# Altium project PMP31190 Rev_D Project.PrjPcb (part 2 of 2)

## Sheet PMP31190 Rev_D Schematic - Charger.SchDoc: Charger
size 431 x 279 mm; Date: Not shown in title block; ApprovedBy: Not shown in title block; CheckedBy: Not shown in title block; Author: Not shown in title block; CompanyName: Not shown in title block; DrawnBy: R. Scibilia; Engineer: Not shown in title block; Organization: Not shown in title block; Address1: Not shown in title block; Address2: Not shown in title block; Address3: Not shown in title block; Address4: Not shown in title block; DocumentNumber: 1; Revision: Use project parameter SCH_Rev; SheetNumber: 2; SheetTotal: 3; PageSetup: Record=PageOptions¦CenterHorizontal=True¦CenterVertical=True¦PrintScale=1.00¦XCorrection=1.00¦YCorrection=1.00¦PrintKind=0¦BorderSize=5000000¦LeftOffset=0¦BottomOffset=0¦Orientation=2¦PaperLength=1000¦PaperWidth=1000¦Scale=100¦PaperSource=15¦PrintQuality=600¦MediaType=1¦DitherType=10¦PaperKind=Letter¦PrintScaleMode=1
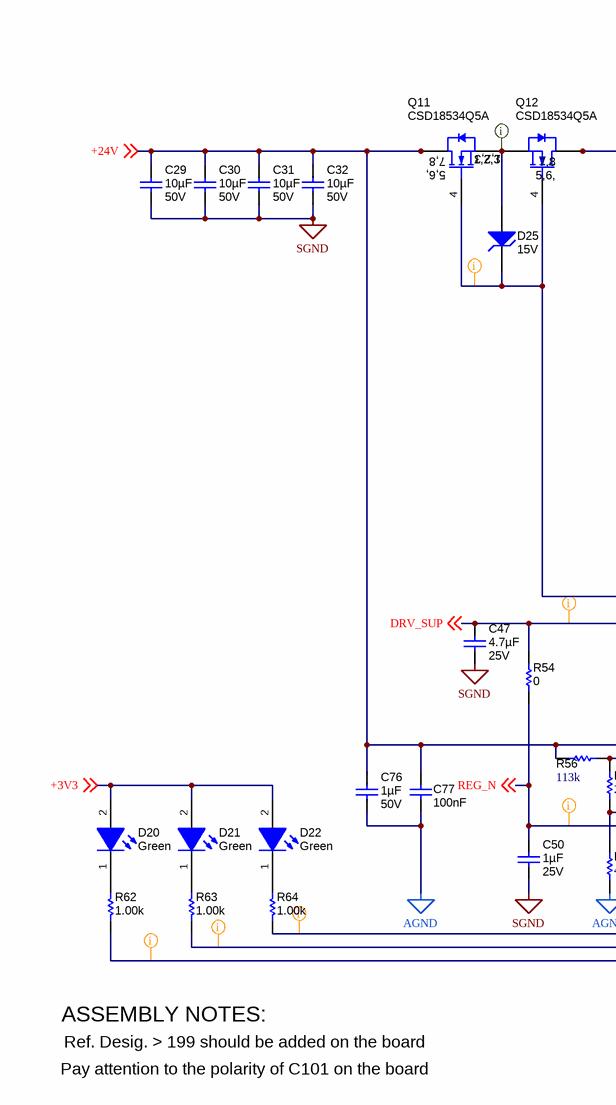
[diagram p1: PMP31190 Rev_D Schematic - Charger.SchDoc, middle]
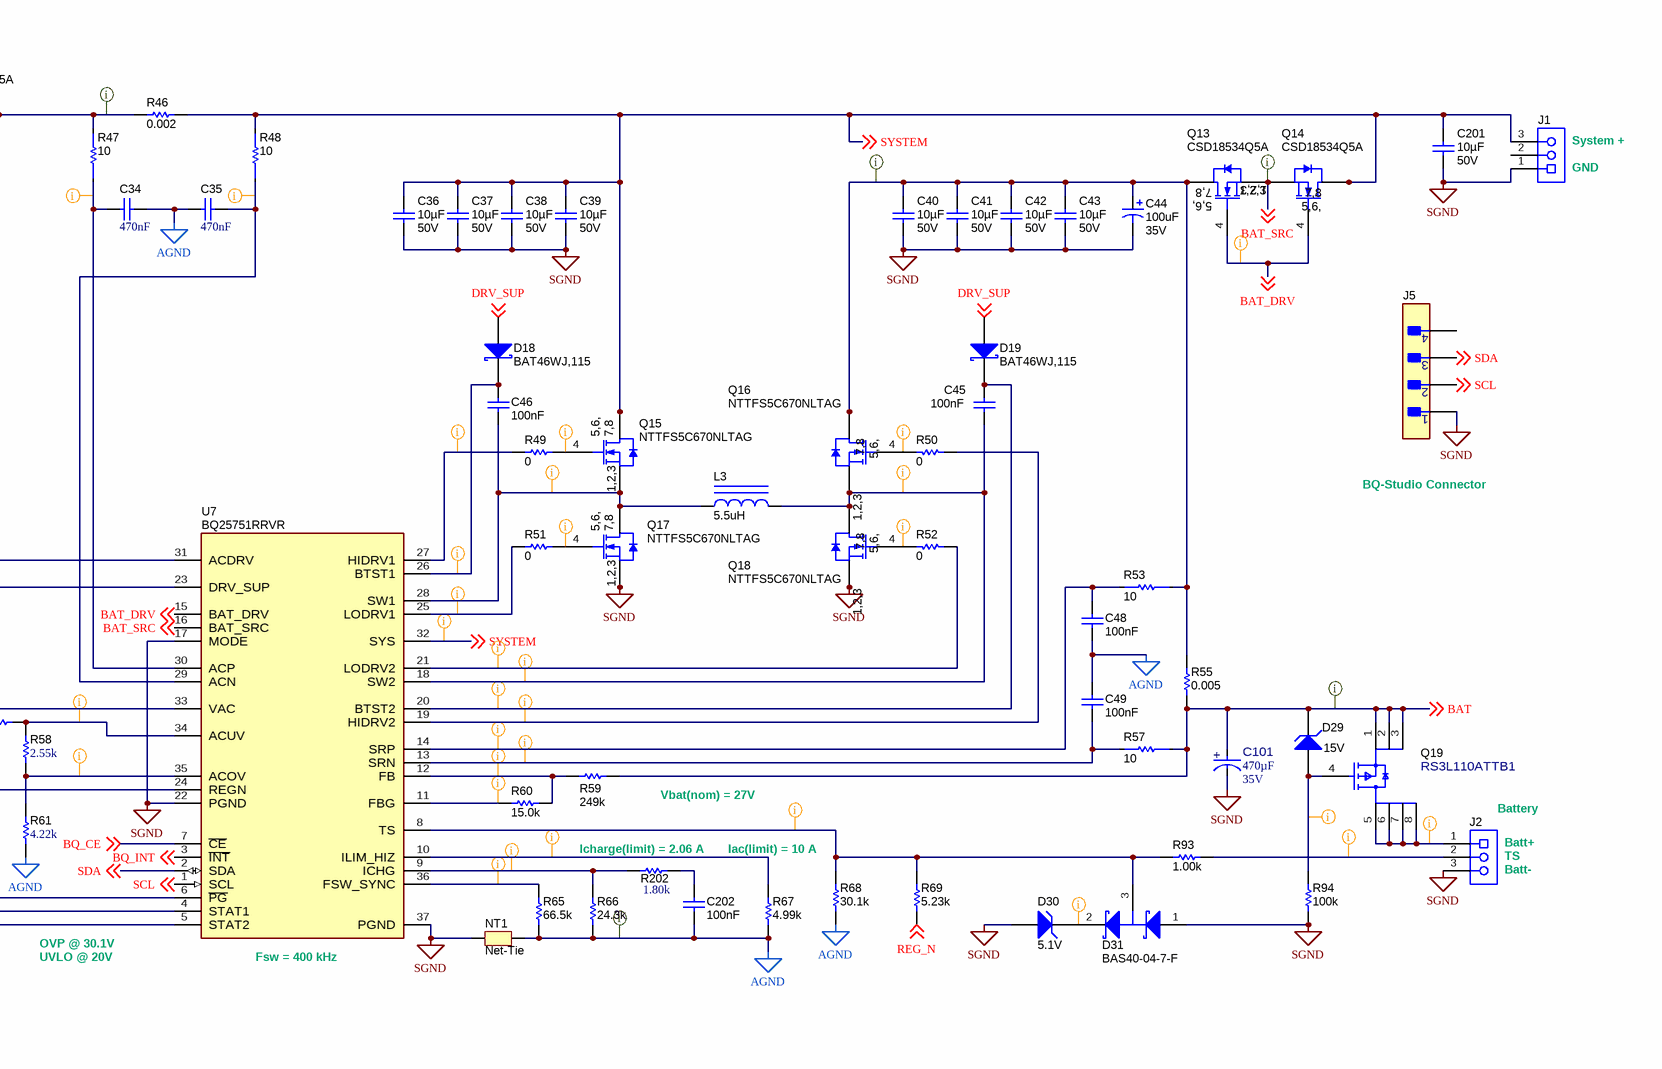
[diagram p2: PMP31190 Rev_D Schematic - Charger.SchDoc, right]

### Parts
C29  VDC_V: 50V  ValueDisplayed: 10µF  [1210_280]  (hidden comment: 885012209073)
C30  VDC_V: 50V  ValueDisplayed: 10µF  [1210_280]  (hidden comment: 885012209073)
C31  VDC_V: 50V  ValueDisplayed: 10µF  [1210_280]  (hidden comment: 885012209073)
C32  VDC_V: 50V  ValueDisplayed: 10µF  [1210_280]  (hidden comment: 885012209073)
C34  Cap_F: 470nF  [0603]  (hidden comment: CGA3E3X7R1H474K080AE)
C35  Cap_F: 470nF  [0603]  (hidden comment: CGA3E3X7R1H474K080AE)
C36  VDC_V: 50V  ValueDisplayed: 10µF  [1210_280]  (hidden comment: 885012209073)
C37  VDC_V: 50V  ValueDisplayed: 10µF  [1210_280]  (hidden comment: 885012209073)
C38  VDC_V: 50V  ValueDisplayed: 10µF  [1210_280]  (hidden comment: 885012209073)
C39  VDC_V: 50V  ValueDisplayed: 10µF  [1210_280]  (hidden comment: 885012209073)
C40  VDC_V: 50V  ValueDisplayed: 10µF  [1210_280]  (hidden comment: 885012209073)
C41  VDC_V: 50V  ValueDisplayed: 10µF  [1210_280]  (hidden comment: 885012209073)
C42  VDC_V: 50V  ValueDisplayed: 10µF  [1210_280]  (hidden comment: 885012209073)
C43  VDC_V: 50V  ValueDisplayed: 10µF  [1210_280]  (hidden comment: 885012209073)
C44  value 100uF  VDC_V: 35V  [WCAP-PTHT_1000x1250]  (hidden comment: 870135675003)
C45  Cap_F: 100nF  [0603]  (hidden comment: 885012206095)
C46  Cap_F: 100nF  [0603]  (hidden comment: 885012206095)
C47  Cap_F: 4.7µF  VDC_V: 25V  [0805_HV]  (hidden comment: 885012107018)
C48  Cap_F: 100nF  [0603]  (hidden comment: 885012206095)
C49  Cap_F: 100nF  [0603]  (hidden comment: 885012206095)
C50  Cap_F: 1µF  VDC_V: 25V  [0603]  (hidden comment: 885012206076)
C76  Cap_F: 1µF  VDC_V: 50V  [0805_HV]  (hidden comment: 885012207103)
C77  Cap_F: 100nF  [0603]  (hidden comment: 885012206095)
C101  ValueDisplayed: 470µF  VDC_V: 35V  [FP-EKZM350ELL681MJ25S_RADIAL-MFG]  (hidden comment: EKZM350ELL471MJ16S)
C201  VDC_V: 50V  ValueDisplayed: 10µF  [1210_280]  (hidden comment: 885012209073)
C202  Cap_F: 100nF  [0603]  (hidden comment: 885012206095)
D18  BAT46WJ,115  [SOD-323F]
D19  BAT46WJ,115  [SOD-323F]
D20  value Green  [WL_SMCW_GREEN_1206]  (hidden comment: 150120VS75000)
D21  value Green  [WL_SMCW_GREEN_1206]  (hidden comment: 150120VS75000)
D22  value Green  [WL_SMCW_GREEN_1206]  (hidden comment: 150120VS75000)
D25  value 15V  [SOD-323]  (hidden comment: MMSZ5245BS-7-F)
D29  value 15V  [SOD-323]  (hidden comment: MMSZ5245BS-7-F)
D30  value 5.1V  [SOD-123]  (hidden comment: MMSZ4689T3G)
D31  BAS40-04-7-F  [SOT-23L]
J1  691236510003  [Wurth_691236510003]  (value not drawn)
J2  691236510003  [Wurth_691236510003]  (value not drawn)
J5  22-05-3041  [FP-22-05-3041_HDR4-MFG]  (value not drawn)
L3  ValueDisplayed: 5.5uH  [WE-HC6]  (hidden comment: 744325550)
NT1  Net-Tie  [Net-Tie_10milWide_30milLong]  (net tie, no BOM)
Q11  CSD18534Q5A  [DQJ0008A]
Q12  CSD18534Q5A  [DQJ0008A]
Q13  CSD18534Q5A  [DQJ0008A]
Q14  CSD18534Q5A  [DQJ0008A]
Q15  NTTFS5C670NLTAG  [Power_WDFN-8]
Q16  NTTFS5C670NLTAG  [Power_WDFN-8]
Q17  NTTFS5C670NLTAG  [Power_WDFN-8]
Q18  NTTFS5C670NLTAG  [Power_WDFN-8]
Q19  RS3L110ATTB1  [FP-SQ9407EY-T1_GE3_SO-8-MFG]
R46  ValueDisplayed: 0.002  [2512]  (hidden comment: 580070763001)
R47  Res_ohm: 10  [FP-560050316012_0603-MFG]  (hidden comment: 560050316012)
R48  Res_ohm: 10  [FP-560050316012_0603-MFG]  (hidden comment: 560050316012)
R49  ValueDisplayed: 0  [0603]  (hidden comment: RMCF0603ZT0R00)
R50  ValueDisplayed: 0  [0603]  (hidden comment: RMCF0603ZT0R00)
R51  ValueDisplayed: 0  [0603]  (hidden comment: RMCF0603ZT0R00)
R52  ValueDisplayed: 0  [0603]  (hidden comment: RMCF0603ZT0R00)
R53  Res_ohm: 10  [FP-560050316012_0603-MFG]  (hidden comment: 560050316012)
R54  ValueDisplayed: 0  [0603]  (hidden comment: RMCF0603ZT0R00)
R55  ValueDisplayed: 0.005  [2512]  (hidden comment: 580070763005)
R56  ValueDisplayed: 113k  [0603]  (hidden comment: RC0603FR-07113KL)
R57  Res_ohm: 10  [FP-560050316012_0603-MFG]  (hidden comment: 560050316012)
R58  ValueDisplayed: 2.55k  [0603]  (hidden comment: RC0603FR-072K55L)
R59  ValueDisplayed: 249k  [0603]  (hidden comment: RC0603FR-07249KL)
R60  ValueDisplayed: 15.0k  [0603]  (hidden comment: RC0603FR-0715KL)
R61  ValueDisplayed: 4.22k  [0603]  (hidden comment: RT0603DRE074K22L)
R62  ValueDisplayed: 1.00k  [0603]  (hidden comment: RC0603FR-071KL)
R63  ValueDisplayed: 1.00k  [0603]  (hidden comment: RC0603FR-071KL)
R64  ValueDisplayed: 1.00k  [0603]  (hidden comment: RC0603FR-071KL)
R65  ValueDisplayed: 66.5k  [0603]  (hidden comment: RC0603FR-0766K5L)
R66  ValueDisplayed: 24.3k  [0603]  (hidden comment: CRCW060324K3FKEA)
R67  ValueDisplayed: 4.99k  [0603]  (hidden comment: RC0603FR-074K99L)
R68  ValueDisplayed: 30.1k  [0603]  (hidden comment: RT0603BRD0730K1L)
R69  ValueDisplayed: 5.23k  [0603]  (hidden comment: RT0603BRD075K23L)
R93  ValueDisplayed: 1.00k  [2010]  (hidden comment: CRCW20101K00FKEF)
R94  ValueDisplayed: 100k  [0603]  (hidden comment: CRCW0603100KDHEAP)
R202  ValueDisplayed: 1.80k  [0603]  (hidden comment: RC0603FR-071K8L)
U7  BQ25751RRVR  [RRV0036A-MFG]

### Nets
AGND: C34.1 C35.2 C48.1 C49.2 C76.2 C77.1 C202.1 NT1.2 R61.1 R65.1 R66.1 R67.1 R68.1
SGND: C29.2 C30.2 C31.2 C32.2 C36.2 C37.2 C38.2 C39.2 C40.2 C41.2 C42.2 C43.2 C44.2(-) C47.2 C50.1 C101.1(CATHODE) C201.2 D30.2(A) D31.1(A) J1.1 J2.3 J5.1 NT1.1 Q17.1(S) Q17.2(S) Q17.3(S) Q18.1(S) Q18.2(S) Q18.3(S) R94.1 U7.17(MODE) U7.22(PGND) U7.37(PGND)
+3V3: D20.2(A) D21.2(A) D22.2(A) ; off-sheet +3V3
+24V: C29.1 C30.1 C31.1 C32.1 C76.1 C77.2 Q11.5(D) Q11.6(D) Q11.7(D) Q11.8(D) Q11.9(D) R56.2 U7.33(VAC) ; off-sheet +24V
BAT: C101.2(ANODE) D29.1(K) Q19.1(S) Q19.2(S) Q19.3(S) R55.1 R57.1 R59.1 ; off-sheet BAT
BAT_DRV: Q13.4(G) Q14.4(G) U7.15(BAT_DRV) ; off-sheet BAT_DRV
BAT_SRC: Q13.1(S) Q13.2(S) Q13.3(S) Q14.1(S) Q14.2(S) Q14.3(S) U7.16(BAT_SRC) ; off-sheet BAT_SRC
BQ_CE: U7.7(~{CE}) ; off-sheet BQ_CE
BQ_INT: U7.3(~{INT}) ; off-sheet BQ_INT
DRV_SUP: C47.1 D18.2(A) D19.2(A) R54.2 U7.23(DRV_SUP) ; off-sheet DRV_SUP
REG_N: C50.2 R54.1 R69.2 U7.24(REGN) ; off-sheet REG_N
SCL: J5.2 U7.1(SCL) ; off-sheet SCL
SDA: J5.3 U7.2(SDA) ; off-sheet SDA
SYSTEM: C36.1 C37.1 C38.1 C39.1 C201.1 J1.3 Q14.5(D) Q14.6(D) Q14.7(D) Q14.8(D) Q14.9(D) Q15.5(D) Q15.6(D) Q15.7(D) Q15.8(D) Q15.9(D) R46.2 R48.2 U7.32(SYS) ; off-sheet SYSTEM
NetC34_2: C34.2 R47.1 U7.30(ACP)
NetC35_1: C35.1 R48.1 U7.29(ACN)
NetC40_1: C40.1 C41.1 C42.1 C43.1 C44.1(+) Q13.5(D) Q13.6(D) Q13.7(D) Q13.8(D) Q13.9(D) Q16.5(D) Q16.6(D) Q16.7(D) Q16.8(D) Q16.9(D) R53.1 R55.2
NetC45_1: C45.1 L3.2 Q16.1(S) Q16.2(S) Q16.3(S) Q18.5(D) Q18.6(D) Q18.7(D) Q18.8(D) Q18.9(D) U7.18(SW2)
NetC45_2: C45.2 D19.1(K) U7.20(BTST2)
NetC46_1: C46.1 L3.1 Q15.1(S) Q15.2(S) Q15.3(S) Q17.5(D) Q17.6(D) Q17.7(D) Q17.8(D) Q17.9(D) U7.28(SW1)
NetC46_2: C46.2 D18.1(K) U7.26(BTST1)
NetC48_2: C48.2 R53.2 U7.14(SRP)
NetC49_1: C49.1 R57.2 U7.13(SRN)
NetC202_2: C202.2 R202.1
NetD20_1: D20.1(K) R62.1
NetD21_1: D21.1(K) R63.1
NetD22_1: D22.1(K) R64.1
NetD25_1: D25.1(K) Q11.4(G) Q12.4(G) U7.31(ACDRV)
NetD25_2: D25.2(A) Q11.1(S) Q11.2(S) Q11.3(S) Q12.1(S) Q12.2(S) Q12.3(S)
NetD29_2: D29.2(A) Q19.4(G) R94.2
NetD30_1: D30.1(K) D31.2(K)
NetD31_3: D31.3(C) R68.2 R69.1 R93.1 U7.8(TS)
NetJ2_1: J2.1 Q19.5(D) Q19.6(D) Q19.7(D) Q19.8(D)
NetJ2_2: J2.2 R93.2
NetQ12_5: Q12.5(D) Q12.6(D) Q12.7(D) Q12.8(D) Q12.9(D) R46.1 R47.2
NetQ15_4: Q15.4(G) R49.2
NetQ16_4: Q16.4(G) R50.1
NetQ17_4: Q17.4(G) R51.1
NetQ18_4: Q18.4(G) R52.1
NetR49_1: R49.1 U7.27(HIDRV1)
NetR50_2: R50.2 U7.19(HIDRV2)
NetR51_2: R51.2 U7.25(LODRV1)
NetR52_2: R52.2 U7.21(LODRV2)
NetR56_1: R56.1 R58.2 U7.34(ACUV)
NetR58_1: R58.1 R61.2 U7.35(ACOV)
NetR59_2: R59.2 R60.1 U7.12(FB)
NetR60_2: R60.2 U7.11(FBG)
NetR62_2: R62.2 U7.5(STAT2)
NetR63_2: R63.2 U7.4(STAT1)
NetR64_2: R64.2 U7.6(~{PG})
NetR65_2: R65.2 U7.36(FSW_SYNC)
NetR66_2: R66.2 R202.2 U7.9(ICHG)
NetR67_2: R67.2 U7.10(ILIM_HIZ)

Not connected (* = marked no-connect by the designer): J1 2; J5 4

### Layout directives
rule Clearance Constraint [Clearance = 10mil]: AGND, BAT, BAT_SRC, NetC40_1, NetD25_2, NetQ12_5
rule Clearance Constraint [Clearance = 9mil]: BAT_DRV, DRV_SUP, NetC34_2, NetC35_1, NetC45_1, NetC45_2, NetC46_1, NetC46_2, NetC48_2, NetC49_1, NetD25_1, NetD29_2, NetD30_1, NetD31_3, NetJ2_1, NetJ2_2, NetQ15_4, NetQ16_4, NetQ17_4, NetQ18_4, NetR49_1, NetR50_2, NetR51_2, NetR52_2, NetR56_1, NetR58_1, NetR59_2, NetR60_2, NetR62_2, NetR63_2, NetR64_2, NetR65_2, NetR66_2, NetR67_2, REG_N, SYSTEM

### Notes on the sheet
- (near J1) System +
- (near J1) GND
- BQ-Studio Connector
- (near R202) Icharge(limit) = 2.06 A
- Vbat(nom) = 27V
- Iac(limit) = 10 A
- (near J2) Battery
- (near J2) Batt+
- (near J2) Batt-
- (near J2) TS
- ASSEMBLY NOTES:
- UVLO @ 20V
- OVP @ 30.1V
- (near U7) Fsw = 400 kHz
- Pay attention to the polarity of C101 on the board
- Ref. Desig. > 199 should be added on the board

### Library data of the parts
C29-C32 C36-C43 C201 = CMP-0081135-1: CAP, CERM, 10 µF, 50 V,+/- 10%, X7R, 1210; Manufacturer: Wuerth; TaMin_C: -55°C; ESR_ohm: 1m; Polarized: N; SizeAreaWB_mm2: 14.7; Value1: 0.001 ohm; U/M: EA; Value: 10uF; TaMax_C: 125°C; SizeZ_mm: 2.8; SizeX_mm: 3.2; SizeY_mm: 2.5; Cap_Case: 1210; SizeArea_mm2: 8; AEC Category: Q200
C34 C35 = CMP-0007097-4: CAP, CERM, 0.47 uF, 50 V, +/- 10%, X7R, AEC-Q200 Grade 1, 0603; Manufacturer: TDK; TaMin_C: -55°C; Polarized: N; SizeAreaWB_mm2: 4.68; Value1: Unknown; U/M: EA; Value: 0.47uF; TaMax_C: 125°C; SizeZ_mm: 1; SizeX_mm: 1.6; SizeY_mm: 0.8; Value2: 50V; SizeArea_mm2: 1.28; AEC Qualified: Y; AEC Category: Q200
C44 = CMP-0079638-1: CAP, Aluminum Polymer, 100 µF, 35 V,+/- 20%, 0.022 ohm, TH; Manufacturer: Wurth Elektronik; SizeAreaWB_mm2: 144; SizeArea_mm2: 100; AEC Qualified: N; AEC Category: Q200; TaMax_C: 125°C; SizeZ_mm: 14; Polarized: Y; TaMin_C: -55°C; SizeY_mm: 10; CompType: Capacitor; ESR_ohm: 22m; Cap_Case: 10x14mm; ValueDisplayed: 100µF
C45 C46 C48 C49 C77 C202 = CMP-0006837-3: CAP, CERM, 0.1 uF, 50 V, +/- 10%, X7R, 0603; Manufacturer: Wurth Elektronik; TaMin_C: -55°C; Polarized: N; SizeAreaWB_mm2: 4.68; Value1: Unknown; U/M: EA; Value: 0.1uF; TaMax_C: 125°C; SizeZ_mm: 1; SizeX_mm: 1.6; SizeY_mm: 0.8; Value2: 50V; SizeArea_mm2: 1.28; AEC Category: Q200
C47 = CMP-0007696-2: CAP, CERM, 4.7 uF, 25 V, +/- 10%, X5R, 0805; Manufacturer: Wurth Elektronik; TaMin_C: -55°C; Polarized: N; SizeAreaWB_mm2: 6.75; Value1: Unknown; U/M: EA; Value: 4.7uF; TaMax_C: 125°C; SizeZ_mm: 1.45; SizeX_mm: 2; SizeY_mm: 1.25; Cap_Case: 0805; SizeArea_mm2: 2.5; AEC Category: Q200
C50 = CMP-0006833-4: CAP, CERM, 1 uF, 25 V, +/- 10%, X7R, 0603; Manufacturer: Wurth Elektronik; TaMin_C: -55°C; Polarized: N; SizeAreaWB_mm2: 4.68; Value1: Unknown; U/M: EA; Value: 1uF; TaMax_C: 125°C; SizeZ_mm: 1; SizeX_mm: 1.6; SizeY_mm: 0.8; SizeArea_mm2: 1.28; AEC Category: Q200
C76 = CMP-0007696-2: CAP, CERM, 1 uF, 50 V, +/- 10%, X7R, 0805; Manufacturer: Wurth Elektronik; TaMin_C: -55°C; Polarized: N; SizeAreaWB_mm2: 6.75; Value1: Unknown; U/M: EA; Value: 1uF; TaMax_C: 125°C; SizeZ_mm: 1.45; SizeX_mm: 2; SizeY_mm: 1.25; Cap_Case: 0805; SizeArea_mm2: 2.5; AEC Category: Q200
C101 = CMP-0001423-1: Cap Aluminum 470uF 35V 20% (10 X 16mm) Radial 5mm; Manufacturer: United Chemi-Con; AEC Qualified: No; IRMS_A: 1.96A; Dissipation Factor: 12%; Leakage Current: 238uA; Life: 10000Hours; Value: 470µF
D18 D19 = CMP-0076946-2: Diode, Schottky, 100 V, 0.25 A, SOD-323F; Manufacturer: Nexperia; SizeAreaWB_mm2: 7.875; Value2: 0.85V; SizeX_mm: 2.5; Green_REACh: Incomplete; SizeArea_mm2: 3.125; Vf_V: 850mV; Green_Lifecycle: Not Set; Vr_V: 100V; TJmax_C: 150°C; Value1: 0.25A; Io_A: 250mA; SizeZ_mm: 0.8; Value: 100V; AEC Category: Q101; SizeY_mm: 1.25
D20-D22 = CMP-0002936-3: LED, Green, SMD; Manufacturer: Wurth Elektronik; Vr_V: 5V; Power_TotalModule: 72mW; Value2: 2V; Value1: 0.072W; Angle: 140; Type: AlInGaP; Io_A: 20mA; Ir_A: 10µA; Tjmax_C: 85°C
D25 D29 = CMP-0005833-4: Diode, Zener, 15 V, 200 mW, SOD-323; Manufacturer: Diodes Inc.; SizeY_mm: 1.35; RJA_CperW: 350; SizeX_mm: 2.7; AEC Category: Q101; SizeAreaWB_mm2: 8.695; SizeZ_mm: 1; Power_W: 200mW; SizeArea_mm2: 3.645; Value1: 0.2W
D30 = CMP-0005786-2: Diode, Zener, 5.1 V, 500 mW, SOD-123; Manufacturer: ON Semiconductor; SizeZ_mm: 1.35; AEC Category: Q101; Power_W: 500mW; SizeArea_mm2: 6.545; SizeX_mm: 3.85; RJA_CperW: 340; SizeY_mm: 1.7; Value1: 0.5W; SizeAreaWB_mm2: 13.095
D31 = CMP-0076970-1: Diode, Schottky, 40 V, 0.2 A, SOT-23; Manufacturer: Diodes Inc.; SizeAreaWB_mm2: 14.0; Vr_V: 40V; SizeArea_mm2: 7.5; TJmax_C: 125°C; AEC Category: Q101; Value: 40V; SizeZ_mm: 1.1; Green_REACh: Incomplete; Io_A: 200mA; Vf_V: 1V; SizeY_mm: 3.0; Green_Lifecycle: Not Set; U/M: EA; Value1: 0.2A; SizeX_mm: 2.5
J1 J2 = CMP-0079043-1: Terminal Block, 5.08mm, 3x1, R/A, TH; Manufacturer: Wurth Elektronik; Pitch_mm: 5.08; Cert_VDE: Y; Gender: Female; Voltage_V: 300V; Current_A: 20A; Row_Count: 1
J5 = CMP-0089047-1: Manufacturer: Molex; Current_A: 4A; Row_Count: 1; Voltage_V: 500V; ContactFinish: Tin,Nickel
L3 = CMP-0063967-1: Inductor, Shielded Drum Core, Superflux, 5.5 uH, 10 A, 0.0112 ohm, SMD; Manufacturer: Wurth Elektronik; Isat: 12A @ 30% inductance drop; Irms: 10A @ 50C rise; Green_Lifecycle: Active; SizeAreaWB_mm2: 158.6; DCR_ohm: 11.2m; Green_REACh: Passed; Value: 5.5uH; Imax_A: 10A; SizeZ_mm: 5; SizeX_mm: 11; SizeY_mm: 10.2; SizeArea_mm2: 112.2; Ind_H: 5.5µH; AEC Category: Q200
NT1 = CMP-0078142-5: Single point connection between nets.
Q11-Q14 = CMP-0000817-1: MOSFET, N-CH, 60 V, 50 A, DQJ0008A (VSONP-8); Alternate Manufacturer: None; Manufacturer: Texas Instruments; SizeZ_mm: 1.1; ChType: N; Value2: 22 nC; Value1: 0.009; VdsMax_V: 60V; SizeX_mm: 6; SizeY_mm: 4.9; Vgs_V: 2.3V; Value: 60V; Rdson45_ohm: 9.8m; SizeArea_mm2: 29.4; AEC Category: Q101; IdsMax_A: 50A; SizeAreaWB_mm2: 55.2; U/M: EA; QgTyp_nC: 22
Q15-Q18 = CMP-0000855-1: MOSFET, N-CH, 60 V, 70 A, 8-PowerWDFN; Alternate Manufacturer: None; Manufacturer: ON Semiconductor; SizeZ_mm: 0.8; ChType: N; Value2: 9 nC; Value1: 0.013; VdsMax_V: 60V; SizeX_mm: 3.3; Vgs_V: 20V; Rdson45_ohm: 13.3m; SizeArea_mm2: 10.89; AEC Category: Q101; IdsMax_A: 70A; SizeAreaWB_mm2: 18.49; U/M: EA; QgTyp_nC: 9.5
Q19 = CMP-0093692-1: P-Channel 60 V 4.6A (Tc) 3.75W (Tc) Surface Mount 8-SOIC; Manufacturer: Rohm Semiconductor; Number Of P Channels: 1; Rdson45_ohm: 12.8m; IdsMax_A: -11A; AEC Grade: Grade 0; ChMode: False; Rthja Max: 100°C/W; Pulse Drain Current: -44A; Standoff Height: 0.1mm; AEC Qualified: Yes; QgTyp_nC: 115nC @ -10V; SizeZ_mm: 1.75mm; Turn On Delay Time: 11ns; Transconductance: 10S; TJmax_C: +175°C; Threshold Vgs Max: -2.5V; Typ Forward Diode Voltage: -0.84V; Vgs_V: 20V; Threshold Vgs Min: -1.5V; Input Capacitace At Vds: 6300pF @ -30V; VdsMax_V: -1.1V; Drain To Source Breakdown Voltage: -60V; Turn Off Delay Time: 36ns; Power_W: 1.4W
R46 = CMP-0015819-2: RES, 0.002, 1%, 2 W, 2512; Manufacturer: Wuerth; Power_W: 2W; TempCo: ppm/C; Value_Code: 2L000; U/M: EA; Value: 0.002; Res_ohm: 2m; SizeX_mm: 6.3; SizeY_mm: 3.2; SizeZ_mm: 0.71; SizeArea_mm2: 20.16; AEC Category: Q200
R47 R48 R53 R57 = CMP-0087986-1: WRIS-KSKE Thick Film Resistors; Manufacturer: Wurth Electronics; Tolerance_%: 1%; AEC Qualified: No; TempCo: 100ppm/°C; Symbol Name: SYM-560050316012; Power_W: 250mW; SizeZ_mm: 0.55mm; VDC_V: 1.5811V
R49-R52 R54 = CMP-0023343-3: RES, 0, 1%, 0.1 W, AEC-Q200 Grade 0, 0603; Manufacturer: Stackpole Electronics Inc; Power_W: 100mW; TempCo: ppm/C; U/M: EA; Value: 0; SizeX_mm: 1.6; SizeY_mm: 0.8; SizeZ_mm: 1; Value2: 0.1W; SizeArea_mm2: 1.28; AEC Qualified: Y; AEC Category: Q200
R55 = CMP-0015814-2: RES, 0.005, 1%, 2 W, 2512; Manufacturer: Wuerth; Power_W: 2W; TempCo: 100 ppm/C; Value_Code: 5L000; U/M: EA; Value: 0.005; EIA_Code: E96; Res_ohm: 5m; SizeX_mm: 6.3; SizeY_mm: 3.2; SizeZ_mm: 0.71; SizeArea_mm2: 20.16; AEC Category: Q200
R56 = CMP-0022754-4: RES, 113 k, 1%, 0.1 W, 0603; Manufacturer: Yageo; Power_W: 100mW; TempCo: 100 ppm/C; Value: 113k; EIA_Code: E96; SizeX_mm: 1.6; SizeY_mm: 0.8; SizeZ_mm: 1; Value2: 0.1W; SizeArea_mm2: 1.28; AEC Qualified: N; VDC_V: 75V; AEC Category: Q200; SizeAreaWB_mm2: 4.68
R58 = CMP-0022992-5: RES, 2.55 k, 1%, 0.1 W, 0603; Manufacturer: Yageo; Power_W: 100mW; TempCo: 100 ppm/C; Value_Code: 2k55; Value: 2.55k; EIA_Code: E96; SizeX_mm: 1.6; SizeY_mm: 0.8; SizeZ_mm: 1; Value2: 0.1W; SizeArea_mm2: 1.28; AEC Qualified: N; VDC_V: 75V; AEC Category: Q200; SizeAreaWB_mm2: 4.68
R59 = CMP-0022941-4: RES, 249 k, 1%, 0.1 W, 0603; Manufacturer: Yageo; Power_W: 100mW; TempCo: 100 ppm/C; Value: 249k; EIA_Code: E96; SizeX_mm: 1.6; SizeY_mm: 0.8; SizeZ_mm: 1; Value2: 0.1W; SizeArea_mm2: 1.28; AEC Qualified: N; VDC_V: 75V; AEC Category: Q200; SizeAreaWB_mm2: 4.68
R60 = CMP-0022816-5: RES, 15.0 k, 1%, 0.1 W, 0603; Manufacturer: Yageo; Power_W: 100mW; TempCo: 100 ppm/C; Value_Code: 15k0; Value: 15.0k; EIA_Code: E96; Res_ohm: 15k; SizeX_mm: 1.6; SizeY_mm: 0.8; SizeZ_mm: 1; Value2: 0.1W; SizeArea_mm2: 1.28; AEC Qualified: N; VDC_V: 75V; AEC Category: Q200; SizeAreaWB_mm2: 4.68
R61 = CMP-0025339-3: RES, 4.22 k, 0.5%, 0.1 W, 0603; Manufacturer: Yageo America; Power_W: 100mW; TempCo: 50 ppm/C; Value_Code: 4k22; U/M: EA; Value: 4.22k; EIA_Code: E192; SizeX_mm: 1.6; SizeY_mm: 0.8; SizeZ_mm: 1; Value2: 0.1W; SizeArea_mm2: 1.28; VDC_V: 75V; AEC Category: Q200
R62-R64 = CMP-0022895-5: RES, 1.00 k, 1%, 0.1 W, 0603; Manufacturer: Yageo; Power_W: 100mW; TempCo: 100 ppm/C; Value_Code: 1k00; Value: 1.00k; EIA_Code: E96; Res_ohm: 1k; SizeX_mm: 1.6; SizeY_mm: 0.8; SizeZ_mm: 1; Value2: 0.1W; SizeArea_mm2: 1.28; AEC Qualified: N; VDC_V: 75V; AEC Category: Q200; SizeAreaWB_mm2: 4.68
R65 = CMP-0023232-5: RES, 66.5 k, 1%, 0.1 W, 0603; Manufacturer: Yageo; Power_W: 100mW; TempCo: 100 ppm/C; Value_Code: 66k5; Value: 66.5k; EIA_Code: E96; SizeZ_mm: 1; Value2: 0.1W; SizeArea_mm2: 1.28; AEC Qualified: N; VDC_V: 75V; AEC Category: Q200; SizeAreaWB_mm2: 4.68; SizeX_mm: 1.6; SizeY_mm: 0.8
R66 = CMP-0022236-4: RES, 24.3 k, 1%, 0.1 W, AEC-Q200 Grade 0, 0603; Manufacturer: Vishay-Dale; Power_W: 100mW; TempCo: 100 ppm/C; Value_Code: 24k3; Value: 24.3k; EIA_Code: E96; SizeX_mm: 1.6; SizeY_mm: 0.8; SizeZ_mm: 1; Value2: 0.1W; SizeArea_mm2: 1.28; AEC Qualified: Y; VDC_V: 75V; AEC Category: Q200; AEC Grade: 0
R67 = CMP-0023155-5: RES, 4.99 k, 1%, 0.1 W, 0603; Manufacturer: Yageo; Power_W: 100mW; TempCo: 100 ppm/C; Value_Code: 4k99; Value: 4.99k; EIA_Code: E96; SizeX_mm: 1.6; SizeY_mm: 0.8; SizeZ_mm: 1; Value2: 0.1W; SizeArea_mm2: 1.28; AEC Qualified: N; VDC_V: 75V; AEC Category: Q200; SizeAreaWB_mm2: 4.68
R68 = CMP-0024096-3: RES, 30.1 k, 0.1%, 0.1 W, 0603; Manufacturer: Yageo America; Power_W: 100mW; TempCo: 25 ppm/C; Value_Code: 30k1; U/M: EA; Value: 30.1k; EIA_Code: E192; SizeX_mm: 1.6; SizeY_mm: 0.8; SizeZ_mm: 1; Value2: 0.1W; SizeArea_mm2: 1.28; VDC_V: 75V; AEC Category: Q200
R69 = CMP-0024368-2: RES, 5.23 k, 0.1%, 0.1 W, 0603; Manufacturer: Yageo America; Power_W: 100mW; TempCo: 25 ppm/C; Value_Code: 5k23; U/M: EA; Value: 5.23k; EIA_Code: E192; SizeX_mm: 1.6; SizeY_mm: 0.8; SizeZ_mm: 1; Value2: 0.1W; SizeArea_mm2: 1.28; VDC_V: 75V; AEC Category: Q200
R93 = CMP-0016277-2: RES, 1.00 k, 1%, 0.75 W, AEC-Q200 Grade 0, 2010; Manufacturer: Vishay-Dale; Power_W: 750mW; TempCo: 100 ppm/C; Value_Code: 1k00; U/M: EA; Value: 1.00k; EIA_Code: E96; Res_ohm: 1k; SizeX_mm: 5; SizeY_mm: 2.5; SizeZ_mm: 1.66; Value2: 0.75W; SizeArea_mm2: 12.5; AEC Qualified: Y; VDC_V: 400V; AEC Grade: 0; AEC Category: Q200
R94 = CMP-0086261-1: RES, 100 k, 0.5%, 0.1 W, AEC-Q200 Grade 0, 0603; Manufacturer: Vishay-Dale; EIA_Code: E192; SizeZ_mm: 1; Power_W: 100mW; Value2: 0.1W; Value: 100k; SizeAreaWB_mm2: 4.68; AEC Qualified: Y; TempCo: 50 ppm/C; SizeArea_mm2: 1.28; AEC Category: Q200; SizeX_mm: 1.6; SizeY_mm: 0.8; AEC Grade: 0
R202 = CMP-0022892-5: RES, 1.80 k, 1%, 0.1 W, 0603; Manufacturer: Yageo; Power_W: 100mW; TempCo: 100 ppm/C; Value_Code: 1k80; Value: 1.80k; Res_ohm: 1.8k; SizeX_mm: 1.6; SizeY_mm: 0.8; SizeZ_mm: 1; Value2: 0.1W; SizeArea_mm2: 1.28; AEC Qualified: N; VDC_V: 75V; AEC Category: Q200; SizeAreaWB_mm2: 4.68
U7 = CMP-0093459-1: 70V, buck-boost, lead acid battery charge controller; Manufacturer: Texas Instruments; SizeZ_mm: 1mm; Standoff Height: 0mm; AEC Qualified: No

## Sheet PMP31190 Rev_D Schematic - LaunchPad Interface.SchDoc: LaunchPad / AC sense / aux supply
size 431 x 279 mm; Date: Not shown in title block; ApprovedBy: Not shown in title block; CheckedBy: Not shown in title block; Author: Not shown in title block; CompanyName: Not shown in title block; DrawnBy: R. Scibilia; Engineer: Not shown in title block; Organization: Not shown in title block; Address1: Not shown in title block; Address2: Not shown in title block; Address3: Not shown in title block; Address4: Not shown in title block; DocumentNumber: 1; Revision: Use project parameter SCH_Rev; SheetNumber: 3; SheetTotal: 3; PageSetup: Record=PageOptions¦CenterHorizontal=True¦CenterVertical=True¦PrintScale=1.00¦XCorrection=1.00¦YCorrection=1.00¦PrintKind=0¦BorderSize=5000000¦LeftOffset=0¦BottomOffset=0¦Orientation=2¦PaperLength=1000¦PaperWidth=1000¦Scale=100¦PaperSource=15¦PrintQuality=600¦MediaType=1¦DitherType=10¦PaperKind=Letter¦PrintScaleMode=1
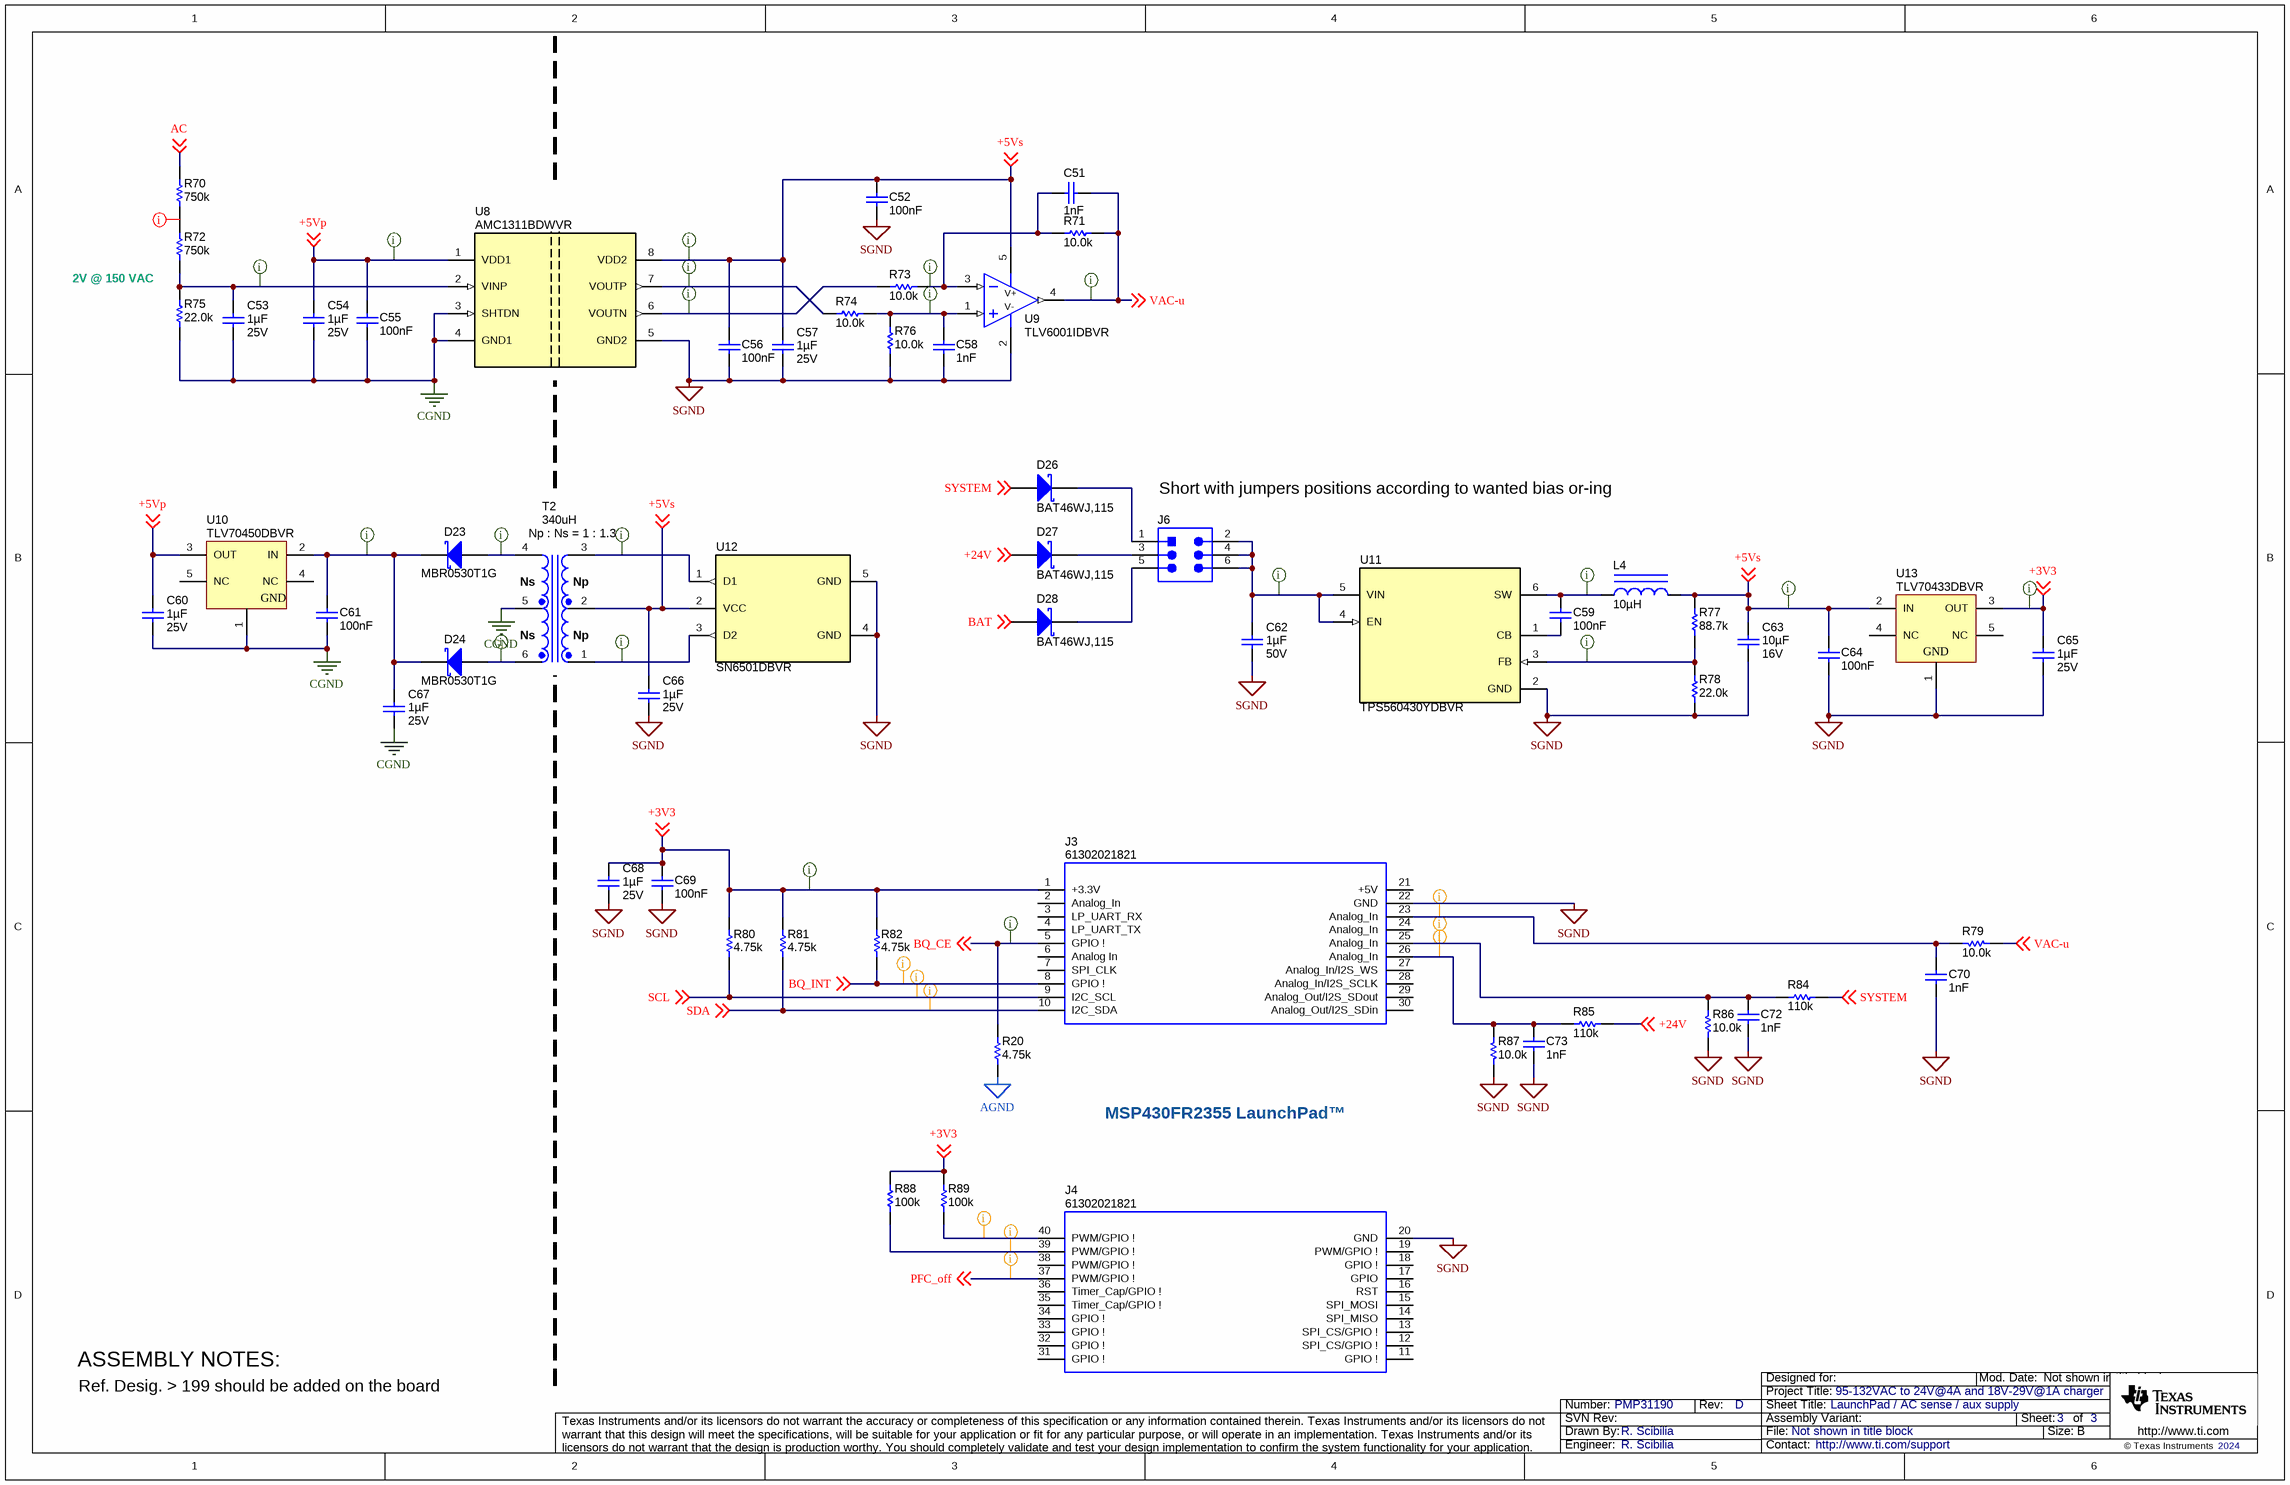
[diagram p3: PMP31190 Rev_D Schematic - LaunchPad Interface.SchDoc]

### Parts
C51  Cap_F: 1nF  [0603]  (hidden comment: 885012206083)
C52  Cap_F: 100nF  [0603]  (hidden comment: 885012206095)
C53  Cap_F: 1µF  VDC_V: 25V  [0603]  (hidden comment: 885012206076)
C54  Cap_F: 1µF  VDC_V: 25V  [0603]  (hidden comment: 885012206076)
C55  Cap_F: 100nF  [0603]  (hidden comment: 885012206095)
C56  Cap_F: 100nF  [0603]  (hidden comment: 885012206095)
C57  Cap_F: 1µF  VDC_V: 25V  [0603]  (hidden comment: 885012206076)
C58  Cap_F: 1nF  [0603]  (hidden comment: 885012206083)
C59  Cap_F: 100nF  [0603]  (hidden comment: 885012206095)
C60  Cap_F: 1µF  VDC_V: 25V  [0603]  (hidden comment: 885012206076)
C61  Cap_F: 100nF  [0603]  (hidden comment: 885012206095)
C62  Cap_F: 1µF  VDC_V: 50V  [0805_HV]  (hidden comment: 885012207103)
C63  VDC_V: 16V  ValueDisplayed: 10µF  [0805_150]  (hidden comment: 885012107014)
C64  Cap_F: 100nF  [0603]  (hidden comment: 885012206095)
C65  Cap_F: 1µF  VDC_V: 25V  [0603]  (hidden comment: 885012206076)
C66  Cap_F: 1µF  VDC_V: 25V  [0603]  (hidden comment: 885012206076)
C67  Cap_F: 1µF  VDC_V: 25V  [0603]  (hidden comment: 885012206076)
C68  Cap_F: 1µF  VDC_V: 25V  [0603]  (hidden comment: 885012206076)
C69  Cap_F: 100nF  [0603]  (hidden comment: 885012206095)
C70  Cap_F: 1nF  [0603]  (hidden comment: 885012206083)
C72  Cap_F: 1nF  [0603]  (hidden comment: 885012206083)
C73  Cap_F: 1nF  [0603]  (hidden comment: 885012206083)
D23  MBR0530T1G  [SOD-123]
D24  MBR0530T1G  [SOD-123]
D26  BAT46WJ,115  [SOD-323F]
D27  BAT46WJ,115  [SOD-323F]
D28  BAT46WJ,115  [SOD-323F]
J3  61302021821  [BoosterPack_40pin_J1J3]
J4  61302021821  [BoosterPack_40pin_J2J4]
J6  HTSW-103-07-G-D  [Samtec_HTSW-103-07-x-D]  (value not drawn)
L4  ValueDisplayed: 10µH  [WE-MAPI_2510]  (hidden comment: 74438323100)
R20  ValueDisplayed: 4.75k  [0603]  (hidden comment: RC0603FR-074K75L)
R70  ValueDisplayed: 750k  [1206]  (hidden comment: RC1206FR-07750KL)
R71  ValueDisplayed: 10.0k  [0603]  (hidden comment: RC0603FR-0710KL)
R72  ValueDisplayed: 750k  [1206]  (hidden comment: RC1206FR-07750KL)
R73  ValueDisplayed: 10.0k  [0603]  (hidden comment: RC0603FR-0710KL)
R74  ValueDisplayed: 10.0k  [0603]  (hidden comment: RC0603FR-0710KL)
R75  ValueDisplayed: 22.0k  [0603]  (hidden comment: RC0603FR-0722KL)
R76  ValueDisplayed: 10.0k  [0603]  (hidden comment: RC0603FR-0710KL)
R77  ValueDisplayed: 88.7k  [0603]  (hidden comment: RC0603FR-0788K7L)
R78  ValueDisplayed: 22.0k  [0603]  (hidden comment: RC0603FR-0722KL)
R79  ValueDisplayed: 10.0k  [0603]  (hidden comment: RC0603FR-0710KL)
R80  ValueDisplayed: 4.75k  [0603]  (hidden comment: RC0603FR-074K75L)
R81  ValueDisplayed: 4.75k  [0603]  (hidden comment: RC0603FR-074K75L)
R82  ValueDisplayed: 4.75k  [0603]  (hidden comment: RC0603FR-074K75L)
R84  ValueDisplayed: 110k  [0603]  (hidden comment: CRCW0603110KFKEA)
R85  ValueDisplayed: 110k  [0603]  (hidden comment: CRCW0603110KFKEA)
R86  ValueDisplayed: 10.0k  [0603]  (hidden comment: RC0603FR-0710KL)
R87  ValueDisplayed: 10.0k  [0603]  (hidden comment: RC0603FR-0710KL)
R88  ValueDisplayed: 100k  [0603]  (hidden comment: CRCW0603100KDHEAP)
R89  ValueDisplayed: 100k  [0603]  (hidden comment: CRCW0603100KDHEAP)
T2  value 340uH  ValueDisplayed: Np : Ns = 1 : 1.3  [Wurth_750313638]  (hidden comment: 750313638)
U8  AMC1311BDWVR  [DWV0008A]
U9  TLV6001IDBVR  [DBV0005A_N]
U10  TLV70450DBVR  [DBV0005A_N]
U11  TPS560430YDBVR  [DBV0006A_N]
U12  SN6501DBVR  [DBV0005A_N]
U13  TLV70433DBVR  [DBV0005A_N]

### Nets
AGND: R20.1
CGND: C53.1 C54.1 C55.1 C60.1 C61.1 C67.1 R75.1 T2.5 U8.3(SHTDN) U8.4(GND1) U10.1(GND)
SGND: C52.1 C56.1 C57.1 C58.2 C62.2 C63.1 C64.1 C65.1 C66.1 C68.1 C69.1 C70.2 C72.2 C73.2 J3.22(GND) J4.20(GND) R76.1 R78.1 R86.2 R87.2 U8.5(GND2) U9.2(V-) U11.2(GND) U12.4(GND) U12.5(GND) U13.1(GND)
+3V3: C65.2 C68.2 C69.2 J3.1(+3.3V) R80.2 R81.2 R82.2 R88.2 R89.2 U13.3(OUT) ; off-sheet +3V3
+5Vp: C54.2 C55.2 C60.2 U8.1(VDD1) U10.3(OUT) ; off-sheet +5Vp
+5Vs: C52.2 C56.2 C57.2 C63.2 C64.2 C66.2 L4.2 R77.2 T2.2 U8.8(VDD2) U9.5(V+) U12.2(VCC) U13.2(IN) ; off-sheet +5Vs
+24V: D27.2(A) R85.2 ; off-sheet +24V
AC: R70.2 ; off-sheet AC
BAT: D28.2(A) ; off-sheet BAT
BQ_CE: J3.5(GPIO_!) R20.2 ; off-sheet BQ_CE
BQ_INT: J3.8(GPIO_!) R82.1 ; off-sheet BQ_INT
PFC_off: J4.37(PWM/GPIO_!) ; off-sheet PFC_off
SCL: J3.9(I2C_SCL) R80.1 ; off-sheet SCL
SDA: J3.10(I2C_SDA) R81.1 ; off-sheet SDA
SYSTEM: D26.2(A) R84.2 ; off-sheet SYSTEM
VAC-u: C51.2 R71.2 R79.1 U9.4(OUT) ; off-sheet VAC-u
NetC51_1: C51.1 R71.1 R73.2 U9.3(IN-)
NetC53_2: C53.2 R72.1 R75.2 U8.2(VINP)
NetC58_1: C58.1 R74.2 R76.2 U9.1(IN+)
NetC59_1: C59.1 U11.1(CB)
NetC59_2: C59.2 L4.1 U11.6(SW)
NetC61_2: C61.2 C67.2 D23.1(K) D24.1(K) U10.2(IN)
NetC62_1: C62.1 J6.2 J6.4 J6.6 U11.4(EN) U11.5(VIN)
NetC70_1: C70.1 J3.23(Analog_In) R79.2
NetC72_1: C72.1 J3.25(Analog_In) R84.1 R86.1
NetC73_1: C73.1 J3.26(Analog_In) R85.1 R87.1
NetD23_2: D23.2(A) T2.4
NetD24_2: D24.2(A) T2.6
NetD26_1: D26.1(K) J6.1
NetD27_1: D27.1(K) J6.3
NetD28_1: D28.1(K) J6.5
NetJ4_39: J4.39(PWM/GPIO_!) R88.1
NetJ4_40: J4.40(PWM/GPIO_!) R89.1
NetR70_1: R70.1 R72.2
NetR73_1: R73.1 U8.6(VOUTN)
NetR74_1: R74.1 U8.7(VOUTP)
NetR77_1: R77.1 R78.2 U11.3(FB)
NetT2_1: T2.1 U12.3(D2)
NetT2_3: T2.3 U12.1(D1)

Not connected (* = marked no-connect by the designer): J3 2(Analog_In) 3(LP_UART_RX) 4(LP_UART_TX) 6(Analog_In) 7(SPI_CLK) 21(+5V) 24(Analog_In) 27(Analog_In/I2S_WS) 28(Analog_In/I2S_SCLK) 29(Analog_Out/I2S_SDout) 30(Analog_Out/I2S_SDin); J4 11(GPIO_!) 12(SPI_CS/GPIO_!) 13(SPI_CS/GPIO_!) 14(SPI_MISO) 15(SPI_MOSI) 16(RST) 17(GPIO) 18(GPIO_!) 19(PWM/GPIO_!) 31(GPIO_!) 32(GPIO_!) 33(GPIO_!) 34(GPIO_!) 35(Timer_Cap/GPIO_!) 36(Timer_Cap/GPIO_!) 38(PWM/GPIO_!); U10 4(NC) 5(NC); U13 4(NC) 5(NC)

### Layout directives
rule Clearance Constraint [Clearance = 10mil]: +3V3, +5Vp, +5Vs, BQ_CE, NetC51_1, NetC53_2, NetC58_1, NetC59_2, NetC61_2, NetC62_1, NetD23_2, NetD24_2, NetR73_1, NetR74_1, NetR77_1, NetT2_1, NetT2_3, VAC-u
rule Clearance Constraint [Clearance = 40mil]: NetR70_1
rule Clearance Constraint [Clearance = 9mil]: BQ_INT, NetC70_1, NetC72_1, NetC73_1, NetJ4_39, NetJ4_40, PFC_off, SCL, SDA

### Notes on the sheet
- 2V @ 150 VAC
- (near J6) Short with jumpers positions according to wanted bias or-ing
- (near T2) Ns
- (near T2) Np
- MSP430FR2355 LaunchPad™
- ASSEMBLY NOTES:
- Ref. Desig. > 199 should be added on the board

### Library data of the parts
C51 C58 C70 C72 C73 = CMP-0064933-4: CAP, CERM, 1000 pF, 50 V,+/- 10%, X7R, 0603; Manufacturer: Wurth Elektronik; TaMin_C: -55°C; Polarized: N; SizeAreaWB_mm2: 4.68; Value1: Unknown; U/M: EA; Value: 1000pF; TaMax_C: 125°C; SizeZ_mm: 1; SizeX_mm: 1.6; SizeY_mm: 0.8; Value2: 50V; SizeArea_mm2: 1.28; AEC Category: Q200
C52 C55 C56 C59 C61 C64 C69 = CMP-0006837-3: as C45 on sheet PMP31190 Rev_D Schematic - Charger
C53 C54 C57 C60 C65-C68 = CMP-0006833-4: as C50 on sheet PMP31190 Rev_D Schematic - Charger
C62 = CMP-0007696-2: as C76 on sheet PMP31190 Rev_D Schematic - Charger
C63 = CMP-0078154-1: CAP, CERM, 10 µF, 16 V,+/- 20%, X5R, 0805; Manufacturer: Wurth Elektronik; TaMin_C: -55°C; Polarized: N; SizeAreaWB_mm2: 6.75; U/M: EA; Value: 10uF; TaMax_C: 85°C; SizeZ_mm: 1.5; SizeX_mm: 2; SizeY_mm: 1.25; Cap_Case: 0805; SizeArea_mm2: 2.5; AEC Category: Q200
D23 D24 = CMP-0028525-2: Diode, Schottky, 30 V, 0.5 A, SOD-123; Manufacturer: ON Semiconductor; Value: 30V; SizeZ_mm: 1.35; SizeAreaWB_mm2: 13.095; Value2: 0.43V; Green_REACh: Passed; Io_A: 500mA; SizeArea_mm2: 6.545; TJmax_C: 125°C; Green_Lifecycle: Active; RJC_CperW: 150; SizeX_mm: 3.85; AEC Category: Q101; SizeY_mm: 1.7; Vf_V: 430mV; Value1: 0.5A
D26-D28 = CMP-0076946-2: as D18 on sheet PMP31190 Rev_D Schematic - Charger
J3 = CMP-0003837-4: Receptacle, 2.54mm, 10x2, Tin, TH; Alternate PartNumber: CRD-081413-A-G; Manufacturer: Wuerth; Alternate Manufacturer: Major League Electronics; Note: Booster Pack 40 pin J1 and J3; Green_Lifecycle: Active; Green_REACh: Incomplete
J4 = CMP-0078266-4: Receptacle, 2.54mm, 10x2, Tin, TH; Alternate PartNumber: CRD-081413-A-G; Manufacturer: Wuerth; Alternate Manufacturer: Major League Electronics; Note: Booster Pack 40 pin J2 and J4; Green_REACh: Incomplete; Green_Lifecycle: Active
J6 = CMP-0055587-1: Header, 2.54mm, 3x2, Gold, TH; Manufacturer: Samtec; CNHeader: TRUE; Green_Lifecycle: Active; Shrouded: N; Gender: Male; Cert_CSA: Y; Green_REACh: Passed; Row_Count: 2; RowSpacing_mm: 2.54; CT: FALSE
L4 = CMP-0750073-1: Inductor, Shielded, Metal Composite, 10 µH, 0.6 A, 0.733 ohm, SMD; Manufacturer: Wurth Elektronik; Value2: 0.6A; SizeZ_mm: 1; Irms: 0.6A @ 40C rise; SizeArea_mm2: 5; DCR_ohm: 0.264; SizeY_mm: 2; Isat: 1.35A @ 20% inductance drop; SizeX_mm: 2.5; Value: 10uH; AEC Category: Q200; AEC Qualified: N; SizeAreaWB_mm2: 10.5
R20 R80-R82 = CMP-0023152-5: RES, 4.75 k, 1%, 0.1 W, 0603; Manufacturer: Yageo; Power_W: 100mW; TempCo: 100 ppm/C; Value_Code: 4k75; Value: 4.75k; EIA_Code: E96; SizeX_mm: 1.6; SizeY_mm: 0.8; SizeZ_mm: 1; Value2: 0.1W; SizeArea_mm2: 1.28; AEC Qualified: N; VDC_V: 75V; AEC Category: Q200; SizeAreaWB_mm2: 4.68
R70 R72 = CMP-0018469-2: RES, 750 k, 1%, 0.25 W, 1206; Manufacturer: Yageo America; Power_W: 250mW; TempCo: 100 ppm/C; U/M: EA; Value: 750k; EIA_Code: E96; SizeX_mm: 3.2; SizeY_mm: 1.6; SizeZ_mm: 1.35; Value2: 0.25W; SizeArea_mm2: 5.12; VDC_V: 200V; AEC Category: Q200
R71 R73 R74 R76 R79 R86 R87 = CMP-0022746-5: RES, 10.0 k, 1%, 0.1 W, 0603; Manufacturer: Yageo; Power_W: 100mW; TempCo: 100 ppm/C; Value_Code: 10k0; Value: 10.0k; EIA_Code: E96; Res_ohm: 10k; SizeX_mm: 1.6; SizeY_mm: 0.8; SizeZ_mm: 1; Value2: 0.1W; SizeArea_mm2: 1.28; AEC Qualified: N; VDC_V: 75V; AEC Category: Q200; SizeAreaWB_mm2: 4.68
R75 R78 = CMP-0022925-5: RES, 22.0 k, 1%, 0.1 W, 0603; Manufacturer: Yageo; Power_W: 100mW; TempCo: 100 ppm/C; Value_Code: 22k0; Value: 22.0k; Res_ohm: 22k; SizeX_mm: 1.6; SizeY_mm: 0.8; SizeZ_mm: 1; Value2: 0.1W; SizeArea_mm2: 1.28; AEC Qualified: N; VDC_V: 75V; AEC Category: Q200; SizeAreaWB_mm2: 4.68
R77 = CMP-0023304-5: RES, 88.7 k, 1%, 0.1 W, 0603; Manufacturer: Yageo; Power_W: 100mW; TempCo: 100 ppm/C; Value_Code: 88k7; Value: 88.7k; EIA_Code: E96; SizeX_mm: 1.6; SizeY_mm: 0.8; SizeZ_mm: 1; Value2: 0.1W; SizeArea_mm2: 1.28; AEC Qualified: N; VDC_V: 75V; AEC Category: Q200; SizeAreaWB_mm2: 4.68
R84 R85 = CMP-0022008-4: RES, 110 k, 1%, 0.1 W, AEC-Q200 Grade 0, 0603; Manufacturer: Vishay-Dale; Power_W: 100mW; TempCo: 100 ppm/C; Value: 110k; EIA_Code: E96; SizeX_mm: 1.6; SizeY_mm: 0.8; SizeZ_mm: 1; Value2: 0.1W; SizeArea_mm2: 1.28; AEC Qualified: Y; VDC_V: 75V; AEC Category: Q200; AEC Grade: 0
R88 R89 = CMP-0086261-1: as R94 on sheet PMP31190 Rev_D Schematic - Charger
T2 = CMP-0030600-1: Transformer, 340 uH, TH; Manufacturer: Wurth Elektronik; DCR_ohm: 0.35; Lp: 340; Ind_H: 340µH
U8 = CMP-0078341-1: Precision, 2-V Input, Reinforced Isolated Amplifier, DWV0008A (SOIC-8); Alternate Manufacturer: Texas Instruments; SizeAreaWB_mm2: 105.975; SizeZ_mm: 2.8; SizeX_mm: 11.5; SizeY_mm: 5.85; SizeArea_mm2: 67.275; CompType: IC; AEC Qualified: N; AEC Category: Q200
U9 = CMP-0073550-1: 1-MHz, Low-Power Operational Amplifier for Cost-Sensitive Systems, DBV0005A (SOT-23-5); Alternate PartNumber: TLV6001UIDBVT; Alternate Manufacturer: Texas Instruments; SizeAreaWB_mm2: 14.82; U/M: EA; SizeZ_mm: 1.45; SizeX_mm: 2.8; SizeY_mm: 2.9; SizeArea_mm2: 8.12; CompType: IC; Value: TLV6001UIDBVR
U10 = CMP-0035558-1: Single Output LDO, 150 mA, Fixed 5 V Output, 2.5 to 24 V Input, with Ultra-Low IQ, 5-pin SOT-23 (DBV), -40 to 125 degC, Green (RoHS & no Sb/Br); Manufacturer: Texas Instruments; Vout Adj(Max)(V): 5; Vin(Min)(V): 2.5; Vin(Max)(V): 24; Accuracy(%): 2; SubFamily: Single Channel LDO; Iout(Max)(A): 0.15; Vdo(Typ)(mV): 400; Iq(Typ)(mA): 0.003
U11 = CMP-0065101-3: 4V to 36 V 0.6 A Synchronous Step-Down Converter, DBV0006A (SOT-23-6); Manufacturer: Texas Instruments; Alternate PartNumber: TPS560430YDBVT; SizeX_mm: 2.8; SizeY_mm: 2.9; CompType: IC; SizeZ_mm: 1.45; SizeArea_mm2: 8.12; SizeAreaWB_mm2: 14.82; U/M: EA
U12 = CMP-0065840-1: Low-Noise 350 mA, 410 kHz Transformer Driver, DBV0005A (SOT-23-5); Alternate PartNumber: SN6501DBVT; Alternate Manufacturer: Texas Instruments; Green_Lifecycle: Not Set; SizeAreaWB_mm2: 14.82; Green_REACh: Passed; U/M: EA; SizeZ_mm: 1.45; SizeX_mm: 2.8; SizeY_mm: 2.9; SizeArea_mm2: 8.12; CompType: IC
U13 = CMP-0035588-1: Single Output LDO, 150 mA, Fixed 3.3 V Output, 2.5 to 24 V Input, with Ultra-Low IQ, 5-pin SOT-23 (DBV), -40 to 125 degC, Green (RoHS & no Sb/Br); Manufacturer: Texas Instruments; Accuracy(%): 2; Vout Adj(Min)(V): 3.3; Vin(Min)(V): 2.5; Vin(Max)(V): 24; SubFamily: Single Channel LDO; Iout(Max)(A): 0.15; Vdo(Typ)(mV): 400; Iq(Typ)(mA): 0.003

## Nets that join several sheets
AGND: PMP31190 Rev_D Schematic - Charger (13 pins), PMP31190 Rev_D Schematic - LaunchPad Interface (R20.1)
CGND: PMP31190 Rev_D Schematic - PFC Flyback (25 pins), PMP31190 Rev_D Schematic - LaunchPad Interface (11 pins)
SGND: PMP31190 Rev_D Schematic - PFC Flyback (18 pins), PMP31190 Rev_D Schematic - Charger (33 pins), PMP31190 Rev_D Schematic - LaunchPad Interface (26 pins)
+3V3: PMP31190 Rev_D Schematic - Charger (D20.2 D21.2 D22.2), PMP31190 Rev_D Schematic - LaunchPad Interface (10 pins)
+24V: PMP31190 Rev_D Schematic - PFC Flyback (12 pins), PMP31190 Rev_D Schematic - Charger (13 pins), PMP31190 Rev_D Schematic - LaunchPad Interface (D27.2 R85.2)
AC: PMP31190 Rev_D Schematic - PFC Flyback (D9.1 D10.1 R15.2), PMP31190 Rev_D Schematic - LaunchPad Interface (R70.2)
BAT: PMP31190 Rev_D Schematic - Charger (8 pins), PMP31190 Rev_D Schematic - LaunchPad Interface (D28.2)
BQ_CE: PMP31190 Rev_D Schematic - Charger (U7.7), PMP31190 Rev_D Schematic - LaunchPad Interface (J3.5 R20.2)
BQ_INT: PMP31190 Rev_D Schematic - Charger (U7.3), PMP31190 Rev_D Schematic - LaunchPad Interface (J3.8 R82.1)
PFC_off: PMP31190 Rev_D Schematic - PFC Flyback (R1.2), PMP31190 Rev_D Schematic - LaunchPad Interface (J4.37)
SCL: PMP31190 Rev_D Schematic - Charger (J5.2 U7.1), PMP31190 Rev_D Schematic - LaunchPad Interface (J3.9 R80.1)
SDA: PMP31190 Rev_D Schematic - Charger (J5.3 U7.2), PMP31190 Rev_D Schematic - LaunchPad Interface (J3.10 R81.1)
SYSTEM: PMP31190 Rev_D Schematic - Charger (19 pins), PMP31190 Rev_D Schematic - LaunchPad Interface (D26.2 R84.2)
